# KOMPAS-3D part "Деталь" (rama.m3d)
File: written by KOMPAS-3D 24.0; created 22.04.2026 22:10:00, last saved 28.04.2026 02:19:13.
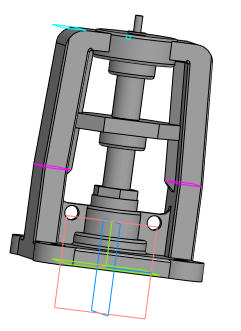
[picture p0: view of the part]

Document properties: Автор: mrdid; Полное имя файла: C:\Работа\ГОТОВЫЕ ИСХОДНИКИ\VSO2130M-F-S Клапан запорный сильфонный DN.ru Ду15-100 Ру40\исходные материалы\DN40\rama.m3d

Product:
- Part/product: Деталь
    Масса: 2.019857

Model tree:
1. Эскиз:2  (with: Ребро.Элемент выдавливания:14)
2. Элемент выдавливания:1
     Расстояние 1 = 10
3. Эскиз:3  (with: Грань.Элемент выдавливания:1, Ребро.Элемент выдавливания:1)
4. Элемент выдавливания:2
     Расстояние 2 = 10
5. Эскиз:4  (with: Грань.Элемент выдавливания:1)
6. Элемент выдавливания:3
     Расстояние 1 = 7
7. Эскиз:5  (with: Грань.Элемент выдавливания:3, Ребро.Элемент выдавливания:3)
8. Элемент выдавливания:4
     Расстояние 1 = 15
9. Эскиз:6  (with: Грань.Элемент выдавливания:1, Ребро.Элемент выдавливания:1)
10. Элемент выдавливания:5
     Расстояние 1 = 40
11. Эскиз:23  (with: Грань.Элемент выдавливания:4, Ребро.Элемент выдавливания:4)
12. Элемент выдавливания:21
     Расстояние 1 = 11
13. Эскиз:7  (with: Грань.Элемент выдавливания:21, Ребро.Элемент выдавливания:3)
14. Элемент выдавливания:6
     Расстояние 2 = 5
15. Эскиз:8  (with: Грань.Элемент выдавливания:5, Ребро.Элемент выдавливания:5)
16. Смещенная плоскость:1  (with: Грань.Элемент выдавливания:5)
17. Эскиз:9
18. Элемент по сечениям:1
19. Элемент по сечениям:2
20. Эскиз:10
21. Элемент выдавливания:8
     Расстояние 2 = 10
22. Эскиз:11  (with: Грань.Элемент выдавливания:8, Ребро.Элемент выдавливания:3)
23. Элемент выдавливания:9  (with: Грань.Элемент выдавливания:8)
     Расстояние 1 = 1; Расстояние 2 = 14; Смещение 2 = 4
24. Эскиз:12  (with: Грань.Элемент выдавливания:9, Ребро.Элемент выдавливания:9)
25. Элемент выдавливания:10
     Расстояние 1 = 8
26. Эскиз:13  (with: Грань.Элемент выдавливания:21, Ребро.Элемент выдавливания:3)
27. Элемент выдавливания:11  (with: Грань.Элемент выдавливания:10)
     Расстояние 1 = 60.838
28. Смещенная плоскость:2  (with: Грань.Элемент выдавливания:21)
29. Эскиз:14  (with: Ребро.Элемент по сечениям:2, Ребро.Элемент по сечениям:1)
30. Элемент выдавливания:12
     Расстояние 1 = 8
31. Эскиз:15  (with: Грань.Элемент выдавливания:12, Ребро.Элемент выдавливания:3)
32. Элемент выдавливания:13
     Расстояние 1 = 8
33. Эскиз:16  (with: Ребро.Элемент выдавливания:5, Ребро.Элемент выдавливания:1, Ребро.Элемент выдавливания:4)
34. Элемент выдавливания:14
     Расстояние 1 = 4
35. Элемент выдавливания:15
     Расстояние 1 = 2
36. Эскиз:17  (with: Ребро.Элемент выдавливания:5, Ребро.Элемент выдавливания:14)
37. Элемент выдавливания:16
     Расстояние 1 = 46.5; Расстояние 2 = 46.5
38. Скругление:1  (with: Ребро.Элемент выдавливания:1, Ребро.Элемент выдавливания:3)
     Радиус = 1.5
39. Скругление:2  (with: Ребро.Элемент выдавливания:9, Ребро.Элемент выдавливания:4, Ребро.Элемент выдавливания:13, Ребро.Элемент выдавливания:10)
40. Эскиз:18  (with: Грань.Элемент выдавливания:9)
41. Элемент выдавливания:17
     Расстояние 1 = 1
42. Скругление:3  (with: Ребро.Элемент по сечениям:2, Ребро.Элемент по сечениям:1)
     Радиус = 10
43. Скругление:4  (with: Ребро.Элемент выдавливания:8)
     Радиус = 1
44. Скругление:5  (with: Ребро.Элемент выдавливания:14)
     Радиус = 5
45. Эскиз:19  (with: Ребро.Элемент выдавливания:17)
46. Элемент выдавливания:18  (with: Грань.Элемент выдавливания:9)
     Смещение 1 = 5
47. Смещенная плоскость:3  (with: Грань.Элемент выдавливания:18)
     Расстояние = 2
48. Эскиз:20  (with: Ребро.Элемент выдавливания:18)
49. Элемент выдавливания:19
     Расстояние 2 = 0.2
50. Скругление:6  (with: Ребро.Элемент выдавливания:18)
     Радиус = 1
51. Эскиз:21  (with: Ребро.Элемент выдавливания:19)
52. Элемент выдавливания:20
     Расстояние 1 = 10
53. Скругление:7  (with: Ребро.Элемент по сечениям:2, Ребро.Элемент выдавливания:5, Ребро.Элемент по сечениям:1)
     Радиус = 1
54. Фаска:1  (with: Ребро.Элемент по сечениям:1, Ребро.Элемент по сечениям:2)
     Угол = 45; Длина 1 = 5; Длина 2 = 5
55. Массив по концентрической сетке:1  (with: Элемент выдавливания:2, Эскиз:3)  (labels: Клапан запорный DN.ru Ду40 Ру40)  (4 pattern instances)
     Шаг 2 = 360
56. Эскиз:24  (with: Грань.Элемент выдавливания:9)
57. Элемент выдавливания:22
     Расстояние 1 = 10

Expressions: v249/2; DN/2; DN/3
Referenced files in C:\Работа\ГОТОВЫЕ ИСХОДНИКИ\VSO2130M-F-S Клапан запорный сильфонный DN.ru Ду15-100 Ру40\исходные материалы\DN40\: VSO2130M-F-S Клапан запорный DN.ru Ду40 Ру40.a3d
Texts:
  DN+5
  DN-10
  Ось Y.Начало координат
